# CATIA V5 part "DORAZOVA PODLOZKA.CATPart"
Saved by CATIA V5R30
Part number: DORAZOVA PODLOZKA
Bounding box of the stored display mesh (mm): x -3 to 5, y -14 to 14, z -14 to 14
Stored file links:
  C:\Users\ondra\Desktop\PŘÍLOHA P III\CATIA\DORAZOVA PODLOZKA.CATPart
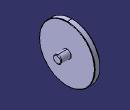
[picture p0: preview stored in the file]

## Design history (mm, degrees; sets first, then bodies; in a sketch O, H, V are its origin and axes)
Set1
  DatumSurface1 to DatumSurface14 "Z55/28x3"
  DatumSurface15 to DatumSurface38 " Z33/4x8"
  Join1: Elements (DatumSurface1; DatumSurface2; DatumSurface3; DatumSurface4; DatumSurface5; DatumSurface6; DatumSurface7; DatumSurface8; DatumSurface9; DatumSurface10; DatumSurface11; DatumSurface12; DatumSurface13; DatumSurface14)
  Join2: Elements (DatumSurface15; DatumSurface16; DatumSurface17; DatumSurface18; DatumSurface19; DatumSurface20; DatumSurface21; DatumSurface22; DatumSurface23; DatumSurface24; DatumSurface25; DatumSurface26; DatumSurface27; DatumSurface28; DatumSurface29; DatumSurface30; DatumSurface31; DatumSurface32; DatumSurface33; DatumSurface34; DatumSurface35; DatumSurface36; DatumSurface37; DatumSurface38)
Body1 (main body)
  CloseSurface1: CloseElement Join1
  CloseSurface2: CloseElement Join2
